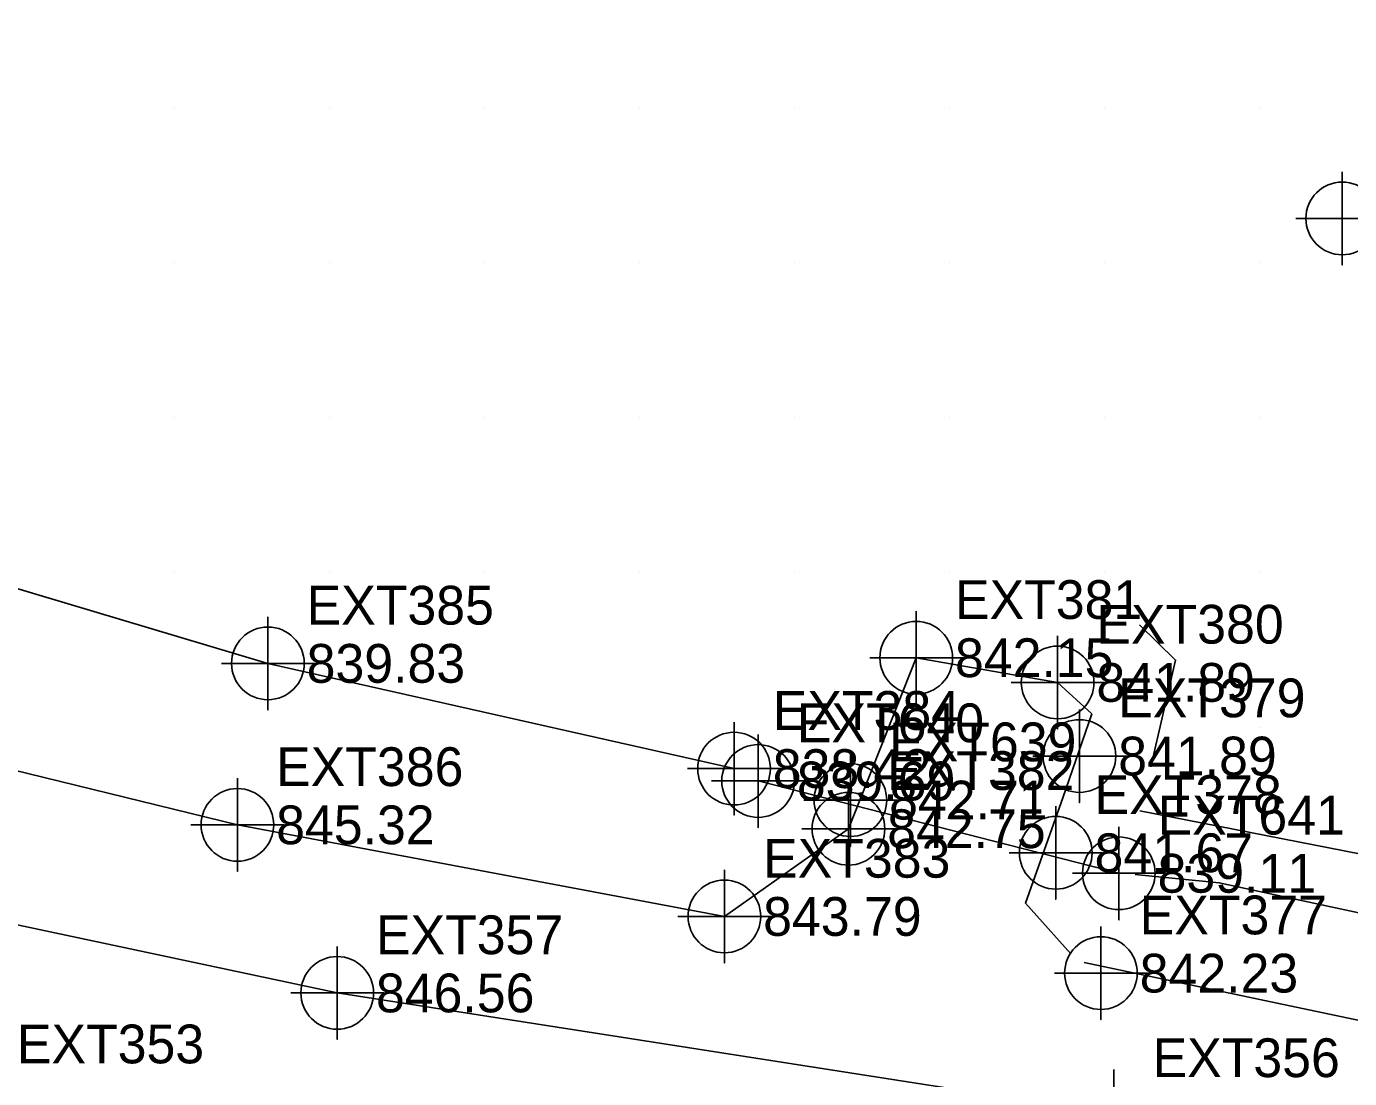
# Model space of a CAD drawing. Extents: x 1762120 to 1766775, y 709485 to 712965.
# Drawn here: x 1762910.4 to 1762995.8, y 712617.4 to 712685.2 of the extents above; entities that cross this region are included whole.
import ezdxf

# ---------------------------------------------------------------- set-up
doc = ezdxf.new("R2010")
doc.units = 0
for name, color, linetype in [('Exist DTM Breakline', 7, 'Continuous'), ('Exist DTM Breakline Cogo Elevation', 7, 'Continuous'), ('Exist DTM Breakline Cogo Number', 7, 'Continuous'), ('Exist DTM Breakline Cogo Point CELL', 7, 'Continuous'), ('Exist DTM Crownline Cogo Number', 7, 'Continuous'), ('Exist DTM Drainline', 7, 'Continuous'), ('Exist DTM Drainline Cogo Elevation', 7, 'Continuous'), ('Exist DTM Drainline Cogo Number', 7, 'Continuous'), ('Exist DTM Drainline Cogo Point CELL', 7, 'Continuous'), ('Exist DTM QL2 LIDAR Elevation Point', 7, 'Continuous'), ('Exist DTM Regular Point CELL', 7, 'Continuous'), ('Exist DTM Regular Point Cogo Elevation', 7, 'Continuous'), ('Exist DTM Regular Point Cogo Number', 7, 'Continuous'), ('Exist Roads EOP', 7, 'Continuous'), ('Exist Roads EOP Cogo Elevation', 7, 'Continuous'), ('Exist Roads EOP Cogo Number', 7, 'Continuous'), ('Exist Roads EOP Cogo Point CELL', 7, 'Continuous'), ('Exist Structure Minor Pipes RCP 15 Inch', 7, 'Continuous'), ('Exist Structure Minor Pipes RCP 15 Inch Cogo Elevation', 7, 'Continuous'), ('Exist Structure Minor Pipes RCP 15 Inch Cogo Number', 7, 'Continuous'), ('Exist Structure Minor Pipes RCP 15 Inch Cogo Point CELL', 7, 'Continuous')]:
    doc.layers.add(name, color=color, linetype=linetype)

msp = doc.modelspace()

# ---------------------------------------------------------------- linework, layer by layer
at = {"layer": 'Exist DTM Breakline'}
for points in [[(1762979.154, 712640.9), (1762976.956, 712642.931), (1762967.832, 712644.521), (1762963.458, 712633.495), (1762955.456, 712627.84), (1762924.041, 712633.746), (1762890.744, 712641.891), (1762864.555, 712651.924), (1762825.229, 712656.054), (1762777.548, 712665.691), (1762763.532, 712670.437)], [(1762982.977, 712637.497), (1762984.564, 712644.374), (1762982.235, 712646.648)], [(1762977.801, 712625.434), (1762974.874, 712628.706), (1762977.281, 712635.482), (1762979.154, 712640.9)], [(1762978.658, 712624.861), (1763000.523, 712620.281), (1763000.478, 712620.273), (1763016.095, 712619.477), (1763018.914, 712622.867), (1763017.313, 712627.895), (1763012.329, 712628.602), (1763008.73, 712629.463), (1762982.253, 712634.642)]]:
    msp.add_lwpolyline(points, dxfattribs=at)
at = {"layer": 'Exist DTM Breakline Cogo Point CELL'}
for points in [[(1762967.832, 712647.521), (1762967.832, 712641.521), (1762967.832, 712644.521), (1762970.832, 712644.521), (1762964.832, 712644.521)], [(1762976.956, 712645.931), (1762976.956, 712639.931), (1762976.956, 712642.931), (1762979.956, 712642.931), (1762973.956, 712642.931)], [(1762978.362, 712641.182), (1762978.362, 712635.182), (1762978.362, 712638.182), (1762981.362, 712638.182), (1762975.362, 712638.182)], [(1762924.041, 712636.746), (1762924.041, 712630.746), (1762924.041, 712633.746), (1762927.041, 712633.746), (1762921.041, 712633.746)], [(1762963.458, 712636.495), (1762963.458, 712630.495), (1762963.458, 712633.495), (1762966.458, 712633.495), (1762960.458, 712633.495)], [(1762976.835, 712634.944), (1762976.835, 712628.944), (1762976.835, 712631.944), (1762979.835, 712631.944), (1762973.835, 712631.944)], [(1762955.456, 712630.84), (1762955.456, 712624.84), (1762955.456, 712627.84), (1762958.456, 712627.84), (1762952.456, 712627.84)], [(1762979.748, 712627.185), (1762979.748, 712621.185), (1762979.748, 712624.185), (1762982.748, 712624.185), (1762976.748, 712624.185)]]:
    msp.add_lwpolyline(points, dxfattribs=at)
for centre in [(1762967.832, 712644.521), (1762976.956, 712642.931), (1762978.362, 712638.182), (1762924.041, 712633.746), (1762963.458, 712633.495), (1762976.835, 712631.944), (1762955.456, 712627.84), (1762979.748, 712624.185)]:
    msp.add_circle(centre, 2.344, dxfattribs=at)
at = {"layer": 'Exist DTM Drainline'}
for points in [[(1762956.078, 712637.37), (1762926.008, 712644.157), (1762891.887, 712654.326), (1762866.923, 712662.338), (1762827.769, 712667.978), (1762778.648, 712676.423), (1762761.216, 712676.604), (1762740.508, 712682.253), (1762728.174, 712682.65)], [(1763015.815, 712622.945), (1763012.902, 712624.529), (1762987.372, 712630.001), (1762981.958, 712630.554)]]:
    msp.add_lwpolyline(points, dxfattribs=at)
at = {"layer": 'Exist DTM Drainline Cogo Point CELL'}
for points in [[(1762926.008, 712647.157), (1762926.008, 712641.157), (1762926.008, 712644.157), (1762929.008, 712644.157), (1762923.008, 712644.157)], [(1762956.078, 712640.37), (1762956.078, 712634.37), (1762956.078, 712637.37), (1762959.078, 712637.37), (1762953.078, 712637.37)]]:
    msp.add_lwpolyline(points, dxfattribs=at)
for centre in [(1762926.008, 712644.157), (1762956.078, 712637.37)]:
    msp.add_circle(centre, 2.344, dxfattribs=at)
at = {"layer": 'Exist DTM QL2 LIDAR Elevation Point'}
for p, q in [((1762920, 712680), (1762920, 712680)), ((1762930, 712680), (1762930, 712680)), ((1762940, 712680), (1762940, 712680)), ((1762950, 712680), (1762950, 712680)), ((1762960, 712680), (1762960, 712680)), ((1762970, 712680), (1762970, 712680)), ((1762980, 712680), (1762980, 712680)), ((1762990, 712680), (1762990, 712680)), ((1762920, 712670), (1762920, 712670)), ((1762930, 712670), (1762930, 712670)), ((1762940, 712670), (1762940, 712670)), ((1762950, 712670), (1762950, 712670)), ((1762960, 712670), (1762960, 712670)), ((1762970, 712670), (1762970, 712670)), ((1762980, 712670), (1762980, 712670)), ((1762990, 712670), (1762990, 712670)), ((1762920, 712660), (1762920, 712660)), ((1762930, 712660), (1762930, 712660)), ((1762940, 712660), (1762940, 712660)), ((1762950, 712660), (1762950, 712660)), ((1762960, 712660), (1762960, 712660)), ((1762970, 712660), (1762970, 712660)), ((1762980, 712660), (1762980, 712660)), ((1762990, 712660), (1762990, 712660)), ((1762920, 712650), (1762920, 712650)), ((1762930, 712650), (1762930, 712650)), ((1762940, 712650), (1762940, 712650)), ((1762950, 712650), (1762950, 712650)), ((1762960, 712650), (1762960, 712650)), ((1762970, 712650), (1762970, 712650)), ((1762980, 712650), (1762980, 712650)), ((1762990, 712650), (1762990, 712650)), ((1762960, 712640), (1762960, 712640)), ((1762990, 712640), (1762990, 712640))]:
    msp.add_line(p, q, dxfattribs=at)
at = {"layer": 'Exist DTM Regular Point CELL'}
for points in [[(1762995.313, 712675.847), (1762995.313, 712669.847), (1762995.313, 712672.847), (1762998.313, 712672.847), (1762992.313, 712672.847)], [(1762963.584, 712638.343), (1762963.584, 712632.343), (1762963.584, 712635.343), (1762966.584, 712635.343), (1762960.584, 712635.343)]]:
    msp.add_lwpolyline(points, dxfattribs=at)
for centre in [(1762995.313, 712672.847), (1762963.584, 712635.343)]:
    msp.add_circle(centre, 2.344, dxfattribs=at)
at = {"layer": 'Exist Roads EOP'}
msp.add_lwpolyline([(1762972.643, 712616.327), (1762930.479, 712622.907), (1762881.99, 712633.196), (1762831.971, 712644.063), (1762782.816, 712654.409), (1762735.737, 712664.412), (1762686.68, 712675.525), (1762639.564, 712685.265), (1762589.399, 712696.151), (1762546.232, 712705.49), (1762496.404, 712716.081), (1762446.151, 712726.895), (1762396.234, 712737.694), (1762346.428, 712748.231), (1762295.972, 712759.182), (1762245.105, 712770.099), (1762193.683, 712780.972), (1762169.004, 712786.417)], dxfattribs=at)
at = {"layer": 'Exist Roads EOP Cogo Point CELL'}
for points in [[(1762930.479, 712625.907), (1762930.479, 712619.907), (1762930.479, 712622.907), (1762933.479, 712622.907), (1762927.479, 712622.907)], [(1762980.58, 712617.979), (1762980.58, 712611.979), (1762980.58, 712614.979), (1762983.58, 712614.979), (1762977.58, 712614.979)]]:
    msp.add_lwpolyline(points, dxfattribs=at)
msp.add_circle((1762930.479, 712622.907), 2.344, dxfattribs=at)
at = {"layer": 'Exist Structure Minor Pipes RCP 15 Inch'}
msp.add_line((1762957.634, 712636.573), (1762980.903, 712630.621), dxfattribs=at)
at = {"layer": 'Exist Structure Minor Pipes RCP 15 Inch Cogo Point CELL'}
for points in [[(1762957.634, 712639.573), (1762957.634, 712633.573), (1762957.634, 712636.573), (1762960.634, 712636.573), (1762954.634, 712636.573)], [(1762980.903, 712633.621), (1762980.903, 712627.621), (1762980.903, 712630.621), (1762983.903, 712630.621), (1762977.903, 712630.621)]]:
    msp.add_lwpolyline(points, dxfattribs=at)
for centre in [(1762957.634, 712636.573), (1762980.903, 712630.621)]:
    msp.add_circle(centre, 2.344, dxfattribs=at)

# ---------------------------------------------------------------- texts
at = {"layer": 'Exist DTM Breakline Cogo Elevation'}
for s, p in [('842.15', (1762970.332, 712643.271)), ('841.89', (1762979.456, 712641.681)), ('841.89', (1762980.862, 712636.932)), ('845.32', (1762926.541, 712632.496)), ('842.75', (1762965.958, 712632.245)), ('841.67', (1762979.335, 712630.694)), ('843.79', (1762957.956, 712626.59)), ('842.23', (1762982.248, 712622.935))]:
    msp.add_text(s, height=2.5, dxfattribs=at).set_placement(p)
at = {"layer": 'Exist DTM Breakline Cogo Number'}
for s, p in [('EXT381', (1762970.332, 712647.021)), ('EXT380', (1762979.456, 712645.431)), ('EXT379', (1762980.862, 712640.682)), ('EXT386', (1762926.541, 712636.246)), ('EXT382', (1762965.958, 712635.995)), ('EXT378', (1762979.335, 712634.444)), ('EXT383', (1762957.956, 712630.34)), ('EXT377', (1762982.248, 712626.685))]:
    msp.add_text(s, height=2.5, dxfattribs=at).set_placement(p)
at = {"layer": 'Exist DTM Crownline Cogo Number'}
msp.add_text('EXT353', height=2.5, dxfattribs=at).set_placement((1762909.818, 712618.367))
at = {"layer": 'Exist DTM Drainline Cogo Elevation'}
for s, p in [('839.83', (1762928.508, 712642.907)), ('838.42', (1762958.578, 712636.12))]:
    msp.add_text(s, height=2.5, dxfattribs=at).set_placement(p)
at = {"layer": 'Exist DTM Drainline Cogo Number'}
for s, p in [('EXT385', (1762928.508, 712646.657)), ('EXT384', (1762958.578, 712639.87))]:
    msp.add_text(s, height=2.5, dxfattribs=at).set_placement(p)
at = {"layer": 'Exist DTM Regular Point Cogo Elevation'}
msp.add_text('842.71', height=2.5, dxfattribs=at).set_placement((1762966.084, 712634.093))
at = {"layer": 'Exist DTM Regular Point Cogo Number'}
msp.add_text('EXT639', height=2.5, dxfattribs=at).set_placement((1762966.084, 712637.843))
at = {"layer": 'Exist Roads EOP Cogo Elevation'}
msp.add_text('846.56', height=2.5, dxfattribs=at).set_placement((1762932.979, 712621.657))
at = {"layer": 'Exist Roads EOP Cogo Number'}
for s, p in [('EXT357', (1762932.979, 712625.407)), ('EXT356', (1762983.08, 712617.479))]:
    msp.add_text(s, height=2.5, dxfattribs=at).set_placement(p)
at = {"layer": 'Exist Structure Minor Pipes RCP 15 Inch Cogo Elevation'}
for s, p in [('839.69', (1762960.134, 712635.323)), ('839.11', (1762983.403, 712629.371))]:
    msp.add_text(s, height=2.5, dxfattribs=at).set_placement(p)
at = {"layer": 'Exist Structure Minor Pipes RCP 15 Inch Cogo Number'}
for s, p in [('EXT640', (1762960.134, 712639.073)), ('EXT641', (1762983.403, 712633.121))]:
    msp.add_text(s, height=2.5, dxfattribs=at).set_placement(p)

doc.saveas('drawing.dxf')
